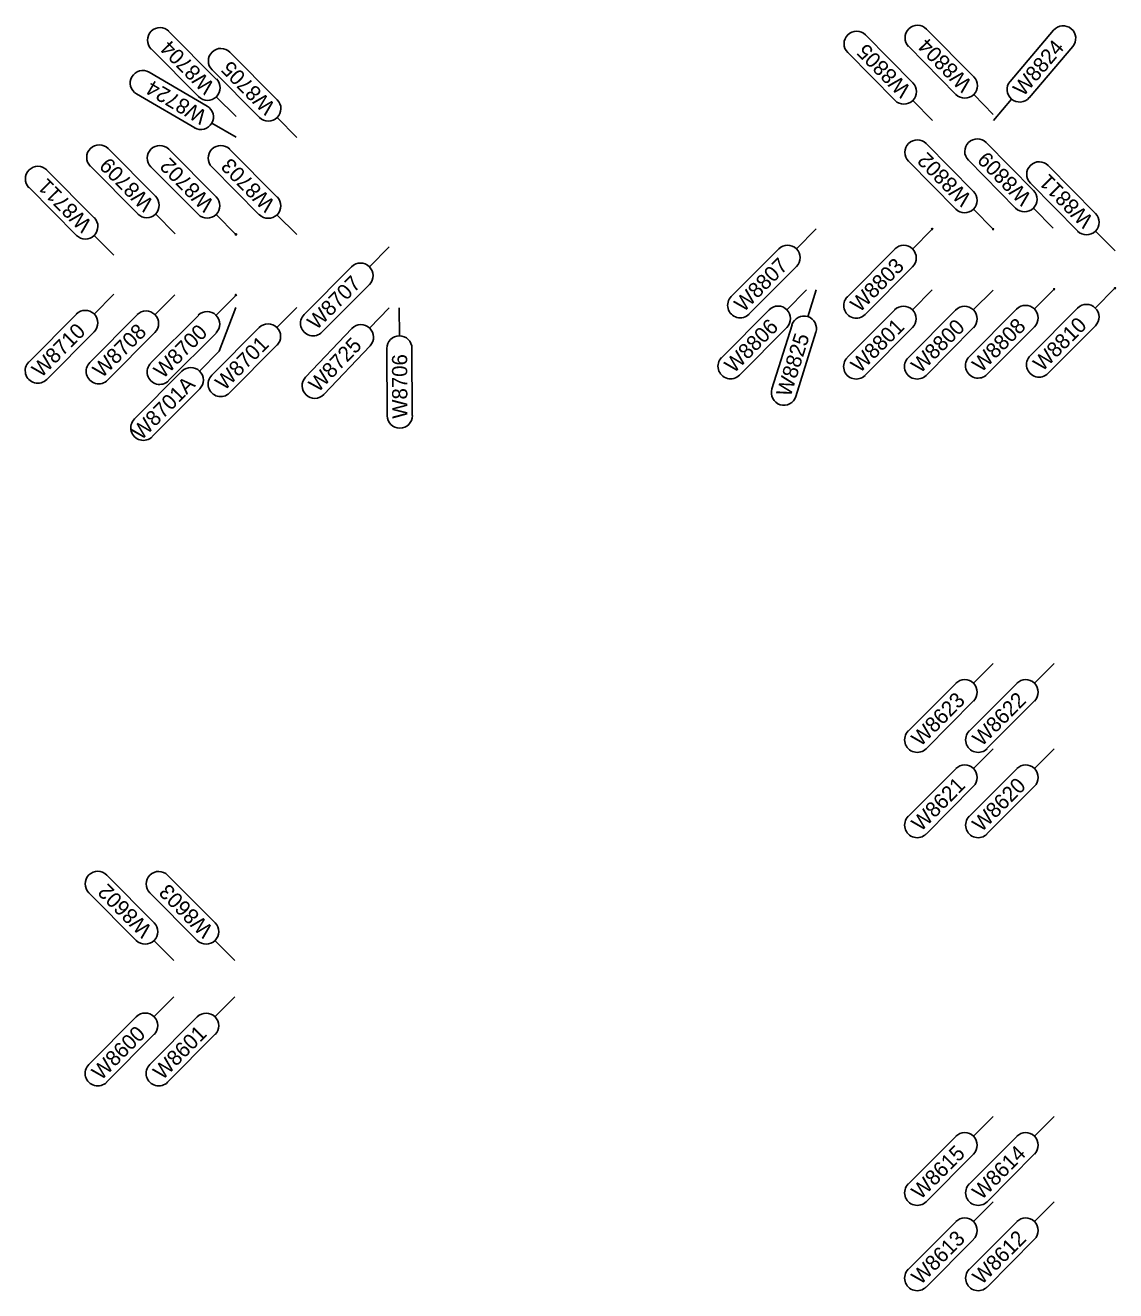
# Model space of a CAD drawing. Extents: x 12479652 to 12487250, y 9842710 to 9846560.
# Drawn here: x 12483661 to 12483750.5, y 9843407.4 to 9843511.2 of the extents above; entities that cross this region are included whole.
import ezdxf

# ---------------------------------------------------------------- set-up
doc = ezdxf.new("R2010")
doc.units = 0
doc.layers.add('_CIVIL_CONSTRUCTION', color=7, linetype='Continuous')
doc.layers.add('TextAlignmentLrg', color=7, linetype='Continuous')

msp = doc.modelspace()

# ---------------------------------------------------------------- linework, layer by layer
at = {"layer": '_CIVIL_CONSTRUCTION'}
for p, q in [((12483676.71, 9843506.81), (12483672.82, 9843510.72)), ((12483733.84, 9843506.51), (12483729.96, 9843510.43)), ((12483738.84, 9843506.99), (12483734.96, 9843510.91)), ((12483745.39, 9843510.82), (12483741.82, 9843506.61)), ((12483671.37, 9843509.28), (12483675.26, 9843505.37)), ((12483733.5, 9843509.47), (12483737.38, 9843505.55)), ((12483743.39, 9843505.28), (12483746.96, 9843509.49)), ((12483681.71, 9843505.1), (12483677.82, 9843509.01)), ((12483728.5, 9843508.99), (12483732.38, 9843505.06)), ((12483675.97, 9843504.59), (12483671.2, 9843507.36)), ((12483676.37, 9843507.57), (12483680.26, 9843503.65)), ((12483670.17, 9843505.59), (12483674.94, 9843502.81)), ((12483678.33, 9843503.73), (12483676.71, 9843505.36)), ((12483735.44, 9843503.42), (12483733.83, 9843505.05)), ((12483740.44, 9843503.9), (12483738.83, 9843505.54)), ((12483740.45, 9843503.41), (12483741.94, 9843505.16)), ((12483678.33, 9843502.03), (12483676.34, 9843503.18)), ((12483683.33, 9843502.02), (12483681.71, 9843503.65)), ((12483671.73, 9843497.19), (12483667.84, 9843501.1)), ((12483676.7, 9843497.14), (12483672.81, 9843501.05)), ((12483681.7, 9843497.13), (12483677.81, 9843501.04)), ((12483738.82, 9843497.58), (12483734.94, 9843501.51)), ((12483743.73, 9843497.66), (12483739.86, 9843501.59)), ((12483733.49, 9843500.07), (12483737.36, 9843496.14)), ((12483738.4, 9843500.15), (12483742.27, 9843496.22)), ((12483748.82, 9843495.79), (12483744.94, 9843499.71)), ((12483666.7, 9843495.43), (12483662.81, 9843499.34)), ((12483666.39, 9843499.65), (12483670.28, 9843495.74)), ((12483671.35, 9843499.61), (12483675.24, 9843495.69)), ((12483676.35, 9843499.6), (12483680.24, 9843495.68)), ((12483661.35, 9843497.9), (12483665.24, 9843493.98)), ((12483743.48, 9843498.27), (12483747.36, 9843494.34)), ((12483673.35, 9843494.1), (12483671.73, 9843495.74)), ((12483678.32, 9843494.06), (12483676.69, 9843495.69)), ((12483683.32, 9843494.05), (12483681.69, 9843495.68)), ((12483740.43, 9843494.5), (12483738.81, 9843496.13)), ((12483745.34, 9843494.58), (12483743.73, 9843496.21)), ((12483725.91, 9843494.51), (12483724.29, 9843492.88)), ((12483668.31, 9843492.35), (12483666.69, 9843493.98)), ((12483735.43, 9843494.5), (12483733.81, 9843492.86)), ((12483750.43, 9843492.7), (12483748.81, 9843494.33)), ((12483690.89, 9843493.04), (12483689.27, 9843491.41)), ((12483718.95, 9843488.96), (12483722.84, 9843492.88)), ((12483728.47, 9843488.95), (12483732.36, 9843492.86)), ((12483683.92, 9843487.49), (12483687.81, 9843491.4)), ((12483724.29, 9843491.43), (12483720.4, 9843487.52)), ((12483733.81, 9843491.41), (12483729.92, 9843487.5)), ((12483689.27, 9843489.96), (12483685.38, 9843486.04)), ((12483725.13, 9843489.51), (12483723.51, 9843487.88)), ((12483725.91, 9843489.51), (12483725.22, 9843487.31)), ((12483735.43, 9843489.5), (12483733.81, 9843487.86)), ((12483740.42, 9843489.49), (12483738.8, 9843487.86)), ((12483745.42, 9843489.57), (12483743.8, 9843487.94)), ((12483750.42, 9843489.65), (12483748.8, 9843488.02)), ((12483668.31, 9843489.15), (12483666.69, 9843487.52)), ((12483673.3, 9843489.11), (12483671.68, 9843487.47)), ((12483678.31, 9843489.06), (12483676.69, 9843487.43)), ((12483661.35, 9843483.61), (12483665.24, 9843487.52)), ((12483666.34, 9843483.56), (12483670.23, 9843487.47)), ((12483671.35, 9843483.51), (12483675.24, 9843487.42)), ((12483676.96, 9843484.47), (12483678.31, 9843488.06)), ((12483683.31, 9843488.05), (12483681.68, 9843486.42)), ((12483690.88, 9843488.04), (12483689.29, 9843486.37)), ((12483691.72, 9843488.04), (12483691.73, 9843485.74)), ((12483718.17, 9843483.96), (12483722.06, 9843487.88)), ((12483728.46, 9843483.95), (12483732.35, 9843487.86)), ((12483733.46, 9843483.94), (12483737.35, 9843487.85)), ((12483738.46, 9843484.02), (12483742.35, 9843487.93)), ((12483743.46, 9843484.1), (12483747.35, 9843488.01)), ((12483676.34, 9843482.5), (12483680.23, 9843486.41)), ((12483684.03, 9843482.35), (12483687.84, 9843486.34)), ((12483723.51, 9843486.43), (12483719.62, 9843482.52)), ((12483722.28, 9843481.38), (12483723.93, 9843486.64)), ((12483733.81, 9843486.41), (12483729.92, 9843482.5)), ((12483738.81, 9843486.41), (12483734.92, 9843482.49)), ((12483743.81, 9843486.49), (12483739.92, 9843482.57)), ((12483748.81, 9843486.57), (12483744.92, 9843482.66)), ((12483666.69, 9843486.07), (12483662.8, 9843482.16)), ((12483671.68, 9843486.02), (12483667.79, 9843482.11)), ((12483676.69, 9843485.97), (12483672.8, 9843482.06)), ((12483725.89, 9843486.03), (12483724.24, 9843480.76)), ((12483676.96, 9843484.47), (12483675.34, 9843482.83)), ((12483681.69, 9843484.97), (12483677.8, 9843481.05)), ((12483689.33, 9843484.92), (12483685.52, 9843480.93)), ((12483690.73, 9843479.19), (12483690.71, 9843484.71)), ((12483692.76, 9843484.71), (12483692.78, 9843479.2)), ((12483670, 9843478.92), (12483673.89, 9843482.83)), ((12483675.35, 9843481.38), (12483671.46, 9843477.47)), ((12483740.43, 9843458.86), (12483738.81, 9843457.23)), ((12483745.43, 9843458.86), (12483743.81, 9843457.23)), ((12483733.47, 9843453.31), (12483737.36, 9843457.22)), ((12483738.47, 9843453.31), (12483742.36, 9843457.22)), ((12483738.81, 9843455.78), (12483734.92, 9843451.86)), ((12483743.81, 9843455.78), (12483739.92, 9843451.87)), ((12483740.43, 9843451.86), (12483738.81, 9843450.23)), ((12483745.43, 9843451.86), (12483743.81, 9843450.23)), ((12483733.47, 9843446.31), (12483737.36, 9843450.22)), ((12483738.47, 9843446.31), (12483742.36, 9843450.22)), ((12483738.81, 9843448.78), (12483734.92, 9843444.86)), ((12483743.81, 9843448.78), (12483739.92, 9843444.87)), ((12483671.61, 9843437.58), (12483667.72, 9843441.49)), ((12483676.61, 9843437.57), (12483672.72, 9843441.48)), ((12483666.26, 9843440.04), (12483670.15, 9843436.13)), ((12483671.26, 9843440.04), (12483675.15, 9843436.12)), ((12483673.22, 9843434.49), (12483671.6, 9843436.13)), ((12483678.22, 9843434.49), (12483676.6, 9843436.12)), ((12483673.22, 9843431.49), (12483671.6, 9843429.86)), ((12483678.22, 9843431.49), (12483676.6, 9843429.86)), ((12483666.26, 9843425.95), (12483670.15, 9843429.86)), ((12483671.26, 9843425.94), (12483675.15, 9843429.85)), ((12483671.6, 9843428.41), (12483667.71, 9843424.5)), ((12483676.6, 9843428.4), (12483672.71, 9843424.49)), ((12483740.44, 9843421.69), (12483738.81, 9843420.06)), ((12483745.44, 9843421.69), (12483743.81, 9843420.06)), ((12483733.47, 9843416.14), (12483737.36, 9843420.05)), ((12483738.47, 9843416.14), (12483742.36, 9843420.05)), ((12483738.82, 9843418.6), (12483734.93, 9843414.69)), ((12483743.82, 9843418.61), (12483739.93, 9843414.69)), ((12483740.44, 9843414.69), (12483738.81, 9843413.06)), ((12483745.44, 9843414.69), (12483743.81, 9843413.06)), ((12483733.47, 9843409.14), (12483737.36, 9843413.05)), ((12483738.47, 9843409.14), (12483742.36, 9843413.05)), ((12483738.82, 9843411.6), (12483734.93, 9843407.69)), ((12483743.82, 9843411.61), (12483739.93, 9843407.69))]:
    msp.add_line(p, q, dxfattribs=at)
for centre, start, end in [((12483734.23, 9843510.19), 44.6553, 224.6553), ((12483746.17, 9843510.15), 319.6719, 139.6719), ((12483672.1, 9843510), 44.8253, 224.8253), ((12483729.23, 9843509.71), 44.6553, 224.6553), ((12483677.09, 9843508.29), 44.8253, 224.8253), ((12483670.68, 9843506.48), 59.7968, 239.7968), ((12483738.11, 9843506.27), 224.6553, 44.6553), ((12483675.99, 9843506.09), 224.8253, 44.8253), ((12483733.11, 9843505.78), 224.6553, 44.6553), ((12483742.6, 9843505.95), 139.6719, 319.6719), ((12483680.98, 9843504.38), 224.8253, 44.8253), ((12483675.45, 9843503.7), 239.7968, 59.7968), ((12483734.21, 9843500.79), 44.6553, 224.6553), ((12483739.13, 9843500.87), 44.6553, 224.6553), ((12483667.11, 9843500.38), 44.8253, 224.8253), ((12483672.08, 9843500.33), 44.8253, 224.8253), ((12483677.08, 9843500.32), 44.8253, 224.8253), ((12483744.21, 9843498.99), 44.6553, 224.6553), ((12483662.08, 9843498.62), 44.8253, 224.8253), ((12483743, 9843496.94), 224.6553, 44.6553), ((12483671, 9843496.46), 224.8253, 44.8253), ((12483675.97, 9843496.42), 224.8253, 44.8253), ((12483680.97, 9843496.41), 224.8253, 44.8253), ((12483738.09, 9843496.86), 224.6553, 44.6553), ((12483748.09, 9843495.06), 224.6553, 44.6553), ((12483665.97, 9843494.71), 224.8253, 44.8253), ((12483723.57, 9843492.15), 315.1702, 135.1702), ((12483733.09, 9843492.14), 315.1702, 135.1702), ((12483688.54, 9843490.68), 315.1702, 135.1702), ((12483719.68, 9843488.24), 135.1702, 315.1702), ((12483729.2, 9843488.22), 135.1702, 315.1702), ((12483748.08, 9843487.29), 315.1702, 135.1702), ((12483665.96, 9843486.8), 315.1702, 135.1702), ((12483670.95, 9843486.75), 315.1702, 135.1702), ((12483675.96, 9843486.7), 315.1702, 135.1702), ((12483684.65, 9843486.77), 135.1702, 315.1702), ((12483722.78, 9843487.15), 315.1702, 135.1702), ((12483724.91, 9843486.33), 342.6175, 162.6175), ((12483733.08, 9843487.14), 315.1702, 135.1702), ((12483738.08, 9843487.13), 315.1702, 135.1702), ((12483743.08, 9843487.21), 315.1702, 135.1702), ((12483680.96, 9843485.69), 315.1702, 135.1702), ((12483688.58, 9843485.63), 316.3572, 136.3572), ((12483691.73, 9843484.71), 0.2337, 180.2337), ((12483662.07, 9843482.88), 135.1702, 315.1702), ((12483667.07, 9843482.83), 135.1702, 315.1702), ((12483672.07, 9843482.78), 135.1702, 315.1702), ((12483674.62, 9843482.11), 315.1702, 135.1702), ((12483718.89, 9843483.24), 135.1702, 315.1702), ((12483729.19, 9843483.22), 135.1702, 315.1702), ((12483734.19, 9843483.22), 135.1702, 315.1702), ((12483739.19, 9843483.3), 135.1702, 315.1702), ((12483744.19, 9843483.38), 135.1702, 315.1702), ((12483677.07, 9843481.78), 135.1702, 315.1702), ((12483684.78, 9843481.64), 136.3572, 316.3572), ((12483723.26, 9843481.07), 162.6175, 342.6175), ((12483691.76, 9843479.19), 180.2337, 0.2337), ((12483670.73, 9843478.19), 135.1702, 315.1702), ((12483738.09, 9843456.5), 315.1702, 135.1702), ((12483743.09, 9843456.5), 315.1702, 135.1702), ((12483734.2, 9843452.59), 135.1702, 315.1702), ((12483739.2, 9843452.59), 135.1702, 315.1702), ((12483738.09, 9843449.5), 315.1702, 135.1702), ((12483743.09, 9843449.5), 315.1702, 135.1702), ((12483734.2, 9843445.59), 135.1702, 315.1702), ((12483739.2, 9843445.59), 135.1702, 315.1702), ((12483666.99, 9843440.77), 44.8253, 224.8253), ((12483671.99, 9843440.76), 44.8253, 224.8253), ((12483670.88, 9843436.85), 224.8253, 44.8253), ((12483675.88, 9843436.85), 224.8253, 44.8253), ((12483670.88, 9843429.14), 315.1702, 135.1702), ((12483675.88, 9843429.13), 315.1702, 135.1702), ((12483666.99, 9843425.22), 135.1702, 315.1702), ((12483671.99, 9843425.22), 135.1702, 315.1702), ((12483738.09, 9843419.33), 315.1702, 135.1702), ((12483743.09, 9843419.33), 315.1702, 135.1702), ((12483734.2, 9843415.42), 135.1702, 315.1702), ((12483739.2, 9843415.42), 135.1702, 315.1702), ((12483738.09, 9843412.33), 315.1702, 135.1702), ((12483743.09, 9843412.33), 315.1702, 135.1702), ((12483734.2, 9843408.42), 135.1702, 315.1702), ((12483739.2, 9843408.42), 135.1702, 315.1702)]:
    msp.add_arc(centre, 1.03, start, end, dxfattribs=at)
at = {"layer": 'TextAlignmentLrg'}
for centre in [(12483735.43, 9843494.5), (12483740.43, 9843494.49), (12483678.32, 9843494.06), (12483745.43, 9843489.57), (12483750.43, 9843489.65), (12483678.31, 9843489.09)]:
    msp.add_circle(centre, 0.05, dxfattribs=at)

# ---------------------------------------------------------------- texts
at = {"layer": '_CIVIL_CONSTRUCTION'}
for s, rotation, p in [('W8804', 134.6553, (12483738.77, 9843506.5)), ('W8704', 134.8253, (12483676.64, 9843506.33)), ('W8805', 134.6553, (12483733.75, 9843506.04)), ('W8824', 49.6719, (12483742.9, 9843505.31)), ('W8705', 134.8253, (12483681.62, 9843504.64)), ('W8724', 149.7968, (12483676.03, 9843504.1)), ('W8802', 134.6553, (12483738.72, 9843497.13)), ('W8809', 134.6553, (12483743.65, 9843497.19)), ('W8709', 134.8253, (12483671.65, 9843496.71)), ('W8702', 134.8253, (12483676.6, 9843496.68)), ('W8703', 134.8253, (12483681.61, 9843496.66)), ('W8711', 134.8253, (12483666.58, 9843494.99)), ('W8811', 134.6553, (12483748.71, 9843495.34)), ('W8807', 45.1702, (12483719.96, 9843487.62)), ('W8803', 45.1702, (12483729.48, 9843487.6)), ('W8707', 45.1702, (12483684.93, 9843486.15)), ('W8710', 45.1702, (12483662.34, 9843482.25)), ('W8708', 45.1702, (12483667.34, 9843482.21)), ('W8700', 45.1702, (12483672.34, 9843482.16)), ('W8806', 45.1702, (12483719.16, 9843482.61)), ('W8801', 45.1702, (12483729.5, 9843482.63)), ('W8800', 45.1702, (12483734.46, 9843482.59)), ('W8808', 45.1702, (12483739.46, 9843482.67)), ('W8810', 45.1702, (12483744.46, 9843482.75)), ('W8701', 45.1702, (12483677.38, 9843481.19)), ('W8725', 46.3572, (12483685.07, 9843481.03)), ('W8825', 72.6175, (12483723.8, 9843480.65)), ('W8706', 90.2337, (12483692.39, 9843478.94)), ('W8701A', 45.1702, (12483670.55, 9843477.11)), ('W8623', 45.1702, (12483734.48, 9843451.97)), ('W8622', 45.1702, (12483739.49, 9843451.98)), ('W8621', 45.1702, (12483734.5, 9843445)), ('W8620', 45.1702, (12483739.47, 9843444.96)), ('W8602', 134.8253, (12483671.51, 9843437.12)), ('W8603', 134.8253, (12483676.52, 9843437.1)), ('W8600', 45.1702, (12483667.26, 9843424.59)), ('W8601', 45.1702, (12483672.29, 9843424.62)), ('W8615', 45.1702, (12483734.48, 9843414.8)), ('W8614', 45.1702, (12483739.47, 9843414.78)), ('W8613', 45.1702, (12483734.48, 9843407.8)), ('W8612', 45.1702, (12483739.49, 9843407.81))]:
    msp.add_text(s, height=1.25, rotation=rotation, dxfattribs=at).set_placement(p)

doc.saveas('drawing.dxf')
